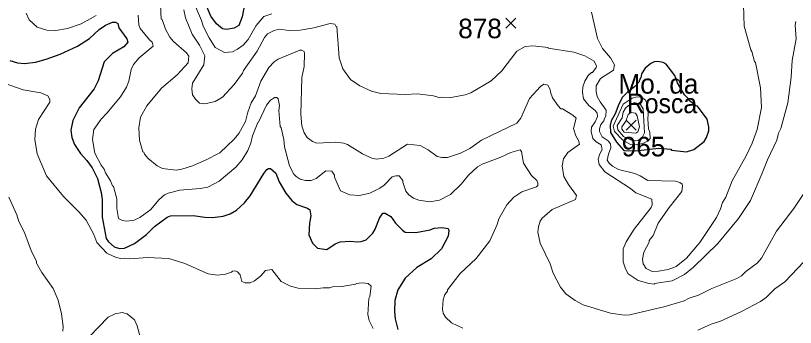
# Model space of a CAD drawing. Extents: x 265.7 to 292.1, y 7676.2 to 7704.2.
# Drawn here: x 267.652 to 270.846, y 7683.888 to 7685.164 of the extents above; entities that cross this region are included whole.
import ezdxf
from ezdxf.enums import TextEntityAlignment as Align

# ---------------------------------------------------------------- set-up
doc = ezdxf.new("R2010")
doc.units = 0
doc.header["$LTSCALE"] = 0.032
for name, color, linetype, lineweight in [('1', 7, 'Continuous', 25), ('2', 7, 'Continuous', 13), ('21', 7, 'Continuous', 25)]:
    doc.layers.add(name, color=color, linetype=linetype, lineweight=lineweight)
doc.layers.add('61', color=7, linetype='Continuous')

msp = doc.modelspace()

# ---------------------------------------------------------------- linework, layer by layer
at = {"layer": '1'}
for points in [[(268.5907, 7685.2156), (268.5804, 7685.1581), (268.5668, 7685.123), (268.5468, 7685.1118), (268.5157, 7685.1071), (268.4998, 7685.1095), (268.475, 7685.1302), (268.4519, 7685.1613), (268.416, 7685.2475)], [(267.6276, 7684.9802), (267.6587, 7684.9698), (267.6874, 7684.9682), (267.7337, 7684.973), (267.7768, 7684.985), (267.8343, 7685.0065), (267.9045, 7685.0384), (267.954, 7685.0696), (267.9939, 7685.1063), (268.0194, 7685.1246), (268.0489, 7685.1374), (268.0609, 7685.1374), (268.0705, 7685.131), (268.0752, 7685.1135), (268.1072, 7685.0688), (268.1119, 7685.0544), (268.0944, 7685.0352), (268.0481, 7685.0089), (268.0138, 7684.9738), (267.9899, 7684.8964), (267.9739, 7684.8645), (267.9125, 7684.7863), (267.8861, 7684.7344), (267.8773, 7684.6953), (267.8821, 7684.665), (267.8933, 7684.6363), (267.9172, 7684.5996), (267.9436, 7684.5708), (267.9659, 7684.5405), (267.9867, 7684.4974), (268.0018, 7684.44), (268.0058, 7684.4113), (268.0058, 7684.3394), (268.0226, 7684.2517), (268.0321, 7684.2373), (268.0553, 7684.2181), (268.0769, 7684.2101), (268.0976, 7684.2125), (268.1383, 7684.2309), (268.1878, 7684.2684), (268.2205, 7684.3003), (268.2723, 7684.3394), (268.2859, 7684.3442), (268.3785, 7684.3458)], [(268.5899, 7684.3977), (268.6123, 7684.4264), (268.6681, 7684.5174), (268.6809, 7684.5333), (268.6881, 7684.5373), (268.6961, 7684.5373), (268.7176, 7684.5182), (268.7312, 7684.4831), (268.7591, 7684.4368), (268.7838, 7684.4065), (268.8038, 7684.3905), (268.8477, 7684.3761), (268.8564, 7684.369), (268.8612, 7684.3442), (268.8556, 7684.3139), (268.8525, 7684.266), (268.8676, 7684.2325), (268.8884, 7684.2125), (268.9267, 7684.207), (268.961, 7684.2293), (268.9817, 7684.2381), (269.0216, 7684.2405), (269.052, 7684.2373), (269.0679, 7684.2389), (269.0879, 7684.2461), (269.115, 7684.274), (269.1246, 7684.29), (269.1429, 7684.3346), (269.1565, 7684.3546), (269.1661, 7684.3554), (269.1884, 7684.3418), (269.2083, 7684.3139), (269.2363, 7684.2852), (269.2483, 7684.278), (269.2913, 7684.2756), (269.3504, 7684.2876), (269.3664, 7684.2939), (269.3983, 7684.2971), (269.4238, 7684.2923), (269.4262, 7684.2844), (269.4238, 7684.2612), (269.3967, 7684.2086), (269.3544, 7684.1679), (269.2961, 7684.1335), (269.2483, 7684.0897), (269.2179, 7684.041), (269.2052, 7683.9979), (269.2036, 7683.9532), (269.2068, 7683.9229), (269.2179, 7683.8798)], [(268.3785, 7684.3458), (268.4264, 7684.3386), (268.4583, 7684.3378), (268.5014, 7684.3426), (268.5301, 7684.353), (268.5572, 7684.3681), (268.5899, 7684.3977)]]:
    msp.add_lwpolyline(points, dxfattribs=at)
msp.add_lwpolyline([(270.1436, 7684.6122), (270.1902, 7684.6103), (270.287, 7684.6209), (270.336, 7684.6165), (270.3391, 7684.6131), (270.4005, 7684.6059), (270.43, 7684.6163), (270.4731, 7684.649), (270.4819, 7684.6642), (270.4915, 7684.6921), (270.4923, 7684.7081), (270.4851, 7684.74), (270.446, 7684.7935), (270.438, 7684.7943), (270.4101, 7684.8174), (270.4093, 7684.8222), (270.3925, 7684.839), (270.3638, 7684.8884), (270.3526, 7684.9188), (270.3175, 7684.965), (270.3048, 7684.9722), (270.2824, 7684.9762), (270.2681, 7684.9746), (270.2537, 7684.9682), (270.2305, 7684.9483), (270.2162, 7684.9251), (270.2138, 7684.9084), (270.2106, 7684.9068), (270.205, 7684.8916), (270.1867, 7684.8717), (270.1595, 7684.8517), (270.138, 7684.8302), (270.1229, 7684.8008), (270.108, 7684.7612), (270.091, 7684.7329), (270.0872, 7684.7159), (270.0891, 7684.6858), (270.1132, 7684.6459)], close=True, dxfattribs=at)
at = {"layer": '2'}
for points in [[(268.7009, 7685.1709), (268.6681, 7685.1597), (268.6378, 7685.1238), (268.6043, 7685.0656), (268.5836, 7685.0432), (268.5604, 7685.0257), (268.5405, 7685.0153), (268.507, 7685.0129), (268.4694, 7685.0329), (268.4447, 7685.072), (268.42, 7685.1198), (268.4136, 7685.1438), (268.3697, 7685.2475)], [(268.2452, 7685.2076), (268.2484, 7685.1486), (268.2516, 7685.1478), (268.2652, 7685.1087), (268.2835, 7685.0752), (268.2979, 7685.0576), (268.3514, 7685.0113), (268.3609, 7684.9978), (268.3585, 7684.9698), (268.313, 7684.9219), (268.25, 7684.8661), (268.1886, 7684.7943), (268.1638, 7684.748), (268.1558, 7684.7049), (268.1598, 7684.6538), (268.1734, 7684.6059), (268.1766, 7684.6051), (268.1798, 7684.5964), (268.1941, 7684.5788), (268.2317, 7684.5485), (268.254, 7684.5373), (268.3099, 7684.5317), (268.3322, 7684.5349), (268.3769, 7684.5493), (268.4296, 7684.5716), (268.4886, 7684.602), (268.5476, 7684.6578), (268.5668, 7684.681), (268.5931, 7684.7304), (268.6027, 7684.7687), (268.6171, 7684.807), (268.6338, 7684.8358), (268.6562, 7684.8948), (268.6897, 7684.9507), (268.7112, 7684.9738), (268.7272, 7684.9858), (268.8158, 7685.0225), (268.8245, 7685.0225), (268.8333, 7685.0169), (268.8357, 7685.0089), (268.8333, 7684.9555), (268.8237, 7684.9108), (268.8205, 7684.7608), (268.8245, 7684.7129), (268.8333, 7684.6842), (268.8461, 7684.665), (268.8676, 7684.649), (268.886, 7684.6419), (268.9642, 7684.6458), (268.9961, 7684.6419), (269.0113, 7684.6363), (269.0727, 7684.598), (269.111, 7684.5796), (269.1302, 7684.5764), (269.1605, 7684.5796), (269.1812, 7684.5884), (269.2578, 7684.6371), (269.3089, 7684.6323), (269.3424, 7684.6147), (269.3791, 7684.5876)], [(270.2413, 7684.489), (270.3558, 7684.4855), (270.3726, 7684.4807), (270.3822, 7684.4743), (270.3846, 7684.4671), (270.3814, 7684.444), (270.3287, 7684.3785), (270.2848, 7684.3139), (270.2633, 7684.2644), (270.2473, 7684.2429), (270.2473, 7684.2365), (270.2258, 7684.1958), (270.2202, 7684.1671), (270.2234, 7684.1479), (270.2353, 7684.1288), (270.2601, 7684.1168), (270.2856, 7684.1176), (270.3255, 7684.1248), (270.3574, 7684.1375), (270.4005, 7684.1711), (270.4548, 7684.2349), (270.5226, 7684.337), (270.5402, 7684.3729), (270.5473, 7684.3985), (270.5609, 7684.4208), (270.5872, 7684.4879), (270.6447, 7684.59), (270.6694, 7684.6411), (270.6894, 7684.6969), (270.7077, 7684.7871), (270.7029, 7684.8677), (270.683, 7684.9714), (270.679, 7684.9754), (270.6686, 7685.0161), (270.6638, 7685.0241), (270.6367, 7685.1198), (270.6335, 7685.2076)], [(267.6954, 7685.1741), (267.7074, 7685.1462), (267.7401, 7685.1158), (267.78, 7685.1047), (267.8167, 7685.1031), (267.8646, 7685.1111), (267.9205, 7685.1294), (267.9811, 7685.1637)], [(268.1542, 7685.1661), (268.1566, 7685.1262), (268.1622, 7685.1103), (268.1997, 7685.064), (268.2117, 7685.0544), (268.2157, 7685.0384), (268.1574, 7684.9914), (268.1343, 7684.9642), (268.1247, 7684.9427), (268.1151, 7684.8948), (268.1056, 7684.8709), (268.0808, 7684.831), (268.0258, 7684.7639), (268.0018, 7684.74), (267.9723, 7684.6969), (267.9667, 7684.657), (267.9763, 7684.6012), (268.0018, 7684.5517), (268.0138, 7684.5357), (268.0194, 7684.5198), (268.0401, 7684.4879), (268.0481, 7684.4671), (268.0529, 7684.4647), (268.0657, 7684.4144), (268.0657, 7684.3745), (268.0729, 7684.3338), (268.0896, 7684.3251), (268.1056, 7684.3219), (268.1375, 7684.3259), (268.1606, 7684.337), (268.2053, 7684.3705), (268.238, 7684.4097), (268.2612, 7684.4296), (268.2763, 7684.4376), (268.3242, 7684.4495), (268.4072, 7684.4559), (268.4391, 7684.4615), (268.4854, 7684.4855), (268.554, 7684.5437), (268.5796, 7684.574), (268.6027, 7684.6123), (268.6155, 7684.6411), (268.6227, 7684.6714), (268.6434, 7684.7264), (268.6474, 7684.728), (268.6801, 7684.7975), (268.6953, 7684.8174), (268.7136, 7684.8286), (268.7216, 7684.8286), (268.728, 7684.823), (268.7328, 7684.7959), (268.7296, 7684.7751), (268.736, 7684.7105), (268.74, 7684.7049), (268.7503, 7684.657), (268.7535, 7684.6267), (268.7735, 7684.5485), (268.791, 7684.515), (268.8006, 7684.5046), (268.8174, 7684.495), (268.8397, 7684.4886), (268.862, 7684.4886), (268.8828, 7684.4974), (268.9227, 7684.5285), (268.9474, 7684.5269), (268.9578, 7684.511), (268.9586, 7684.503), (268.9825, 7684.4472), (269.0216, 7684.4304), (269.0599, 7684.4272), (269.103, 7684.4376), (269.1437, 7684.4575), (269.1613, 7684.4703), (269.194, 7684.5038), (269.21, 7684.5086), (269.2235, 7684.5078), (269.2387, 7684.4894), (269.2387, 7684.4815), (269.2506, 7684.4448), (269.2626, 7684.4296)], [(268.3402, 7685.1877), (268.3482, 7685.155), (268.3745, 7685.0879), (268.4056, 7685.0432), (268.4272, 7684.9986), (268.4232, 7684.9626), (268.3769, 7684.8868), (268.3737, 7684.8645), (268.3769, 7684.839), (268.3888, 7684.8214), (268.4056, 7684.8054), (268.4264, 7684.8022), (268.4694, 7684.8126), (268.4998, 7684.8302), (268.5468, 7684.882), (268.5812, 7684.9283), (268.5859, 7684.9395), (268.641, 7685.0177), (268.6713, 7685.0736), (268.6833, 7685.0887), (268.7104, 7685.1031), (268.7296, 7685.1079), (268.7727, 7685.1023), (268.8174, 7685.1047), (268.8732, 7685.1142), (268.9402, 7685.131), (268.9594, 7685.1286), (268.9634, 7685.1206), (268.9674, 7685.119), (268.9777, 7684.9906), (268.9921, 7684.9459), (269.024, 7684.9028), (269.0615, 7684.8757), (269.1094, 7684.8549), (269.1477, 7684.8453), (269.2483, 7684.8413), (269.2977, 7684.8429), (269.3632, 7684.835), (269.3855, 7684.8286), (269.3967, 7684.8302), (269.4286, 7684.827), (269.494, 7684.8398), (269.5164, 7684.8477), (269.5994, 7684.8972), (269.644, 7684.9371), (269.7047, 7685.0177), (269.739, 7685.0376), (269.7701, 7685.04), (269.834, 7685.0329), (269.834, 7685.0305), (269.9393, 7685.0137), (269.984, 7684.9993), (270.0215, 7684.9778), (270.0311, 7684.9571), (270.0303, 7684.9515)], [(270.0111, 7685.1773), (270.0358, 7685.0704), (270.0566, 7685.0289), (270.0885, 7684.9914), (270.1053, 7684.9618), (270.1013, 7684.9403), (270.0478, 7684.906), (270.0303, 7684.8757), (270.0303, 7684.8533), (270.0342, 7684.8326), (270.0462, 7684.8102), (270.0717, 7684.7767), (270.0702, 7684.752), (270.0638, 7684.7432), (270.0622, 7684.7336), (270.0494, 7684.7185), (270.0438, 7684.7001), (270.0438, 7684.6889), (270.055, 7684.6682), (270.0789, 7684.6506), (270.0885, 7684.6395), (270.0901, 7684.6219), (270.0805, 7684.5964), (270.0757, 7684.5716), (270.0829, 7684.5597), (270.0965, 7684.5477), (270.1212, 7684.5341), (270.1883, 7684.5174), (270.2106, 7684.5078), (270.2413, 7684.489)], [(269.9736, 7684.8501), (269.9784, 7684.823), (270.0007, 7684.7959), (270.0255, 7684.7751), (270.0342, 7684.7639), (270.035, 7684.7512), (270.0255, 7684.7288), (270.0111, 7684.7065), (270.0095, 7684.6897), (270.0167, 7684.6602), (270.0303, 7684.6474), (270.051, 7684.6355), (270.0542, 7684.6155), (270.0446, 7684.598), (270.0382, 7684.5756), (270.043, 7684.5549), (270.0654, 7684.5245), (270.1707, 7684.4559), (270.193, 7684.4384), (270.2577, 7684.412), (270.2601, 7684.3889), (270.2561, 7684.3785), (270.1859, 7684.2892), (270.1531, 7684.2381), (270.1404, 7684.2086), (270.1412, 7684.1559), (270.1499, 7684.1272), (270.1611, 7684.1072), (270.2026, 7684.0793), (270.2457, 7684.0673), (270.2688, 7684.0649), (270.2696, 7684.0673), (270.3415, 7684.0785), (270.3925, 7684.1048), (270.4292, 7684.1343), (270.529, 7684.2317), (270.6128, 7684.3338), (270.6622, 7684.4065), (270.7109, 7684.5182), (270.7317, 7684.574), (270.77, 7684.6538), (270.7779, 7684.6826), (270.7867, 7684.7017), (270.8155, 7684.807), (270.829, 7684.9124), (270.833, 7684.9794), (270.849, 7685.0688), (270.845, 7685.1246), (270.8482, 7685.1398)], [(270.0303, 7684.9515), (270.0151, 7684.9315), (270.0111, 7684.9315), (269.9975, 7684.918), (269.9832, 7684.8948), (269.9752, 7684.8725), (269.9736, 7684.8501)], [(267.6084, 7684.886), (267.6827, 7684.8605), (267.7545, 7684.8477), (267.7832, 7684.835), (267.792, 7684.8198), (267.7912, 7684.8094), (267.7457, 7684.7384), (267.7329, 7684.6985)], [(269.7055, 7684.724), (269.7214, 7684.744), (269.7566, 7684.8246), (269.802, 7684.8741), (269.8164, 7684.8836), (269.8324, 7684.8796), (269.8419, 7684.8613), (269.8427, 7684.8501), (269.8507, 7684.8278), (269.8739, 7684.7943), (269.8858, 7684.7823), (269.8922, 7684.7815), (269.9345, 7684.756), (269.9489, 7684.744), (269.9377, 7684.7017), (269.9465, 7684.6714), (269.9584, 7684.6522), (269.9616, 7684.6371), (269.9146, 7684.6036), (269.897, 7684.5772), (269.8906, 7684.5485), (269.8978, 7684.5054), (269.9169, 7684.4719), (269.9497, 7684.4272), (269.9457, 7684.4105), (269.8499, 7684.3697), (269.8084, 7684.3354), (269.8004, 7684.3219), (269.7933, 7684.2995), (269.7917, 7684.2772), (269.8004, 7684.2325), (269.8419, 7684.1479), (269.8547, 7684.1096), (269.8834, 7684.0522), (269.9058, 7684.025), (269.9441, 7683.9979), (269.9776, 7683.9803), (270.0893, 7683.946), (270.1452, 7683.9381), (270.1675, 7683.9396), (270.3127, 7683.9732), (270.3909, 7683.9971), (270.4117, 7684.0075), (270.45, 7684.0202), (270.5043, 7684.0466), (270.6064, 7684.0881), (270.6255, 7684.0992), (270.6431, 7684.116), (270.6902, 7684.1511), (270.7077, 7684.1711), (270.7692, 7684.282), (270.8394, 7684.3745), (270.8921, 7684.4527)], [(269.3791, 7684.5876), (269.3983, 7684.5828), (269.4206, 7684.5828), (269.4749, 7684.6004), (269.5132, 7684.6203), (269.5603, 7684.6538), (269.7055, 7684.724)], [(267.7329, 7684.6985), (267.7305, 7684.657), (267.7401, 7684.598), (267.7784, 7684.5086), (267.8478, 7684.4232), (267.9109, 7684.361), (267.9412, 7684.3259)], [(269.4765, 7684.4743), (269.5076, 7684.511), (269.5435, 7684.5445), (269.5635, 7684.5557), (269.6393, 7684.5844), (269.6808, 7684.6036), (269.7191, 7684.6147), (269.7246, 7684.6075), (269.7326, 7684.5597), (269.7653, 7684.5094), (269.7869, 7684.4894), (269.7909, 7684.4799), (269.7909, 7684.4687), (269.7861, 7684.4631), (269.7254, 7684.4424), (269.6927, 7684.42), (269.6648, 7684.3897), (269.6321, 7684.3315), (269.6249, 7684.3091), (269.5946, 7684.2421), (269.5379, 7684.1703), (269.4733, 7684.108), (269.4214, 7684.0418), (269.4214, 7684.0354), (269.4102, 7684.0218), (269.4031, 7684.0011), (269.4007, 7683.9628), (269.4039, 7683.946), (269.4126, 7683.9293), (269.4374, 7683.9061), (269.4845, 7683.8846)], [(269.2626, 7684.4296), (269.2818, 7684.4168), (269.3041, 7684.4089), (269.3488, 7684.4017), (269.3887, 7684.4089), (269.4334, 7684.4312), (269.4765, 7684.4743)], [(267.8454, 7683.8718), (267.847, 7683.8918), (267.8391, 7683.9436), (267.8263, 7683.9995), (267.8055, 7684.0474), (267.7593, 7684.1128), (267.7369, 7684.1511), (267.7369, 7684.1583), (267.7162, 7684.199), (267.689, 7684.2724), (267.6635, 7684.3251), (267.6571, 7684.349), (267.6236, 7684.4208)], [(267.9412, 7684.3259), (267.9723, 7684.2676), (267.9843, 7684.2357), (268.025, 7684.191), (268.0641, 7684.1735), (268.0832, 7684.1695), (268.096, 7684.1711), (268.1199, 7684.1679), (268.1918, 7684.1735), (268.2795, 7684.1695), (268.345, 7684.1487), (268.4407, 7684.1072), (268.479, 7684.1016), (268.5109, 7684.1056), (268.5365, 7684.1136), (268.5405, 7684.1184), (268.5508, 7684.1192), (268.5604, 7684.1152), (268.5716, 7684.1032), (268.5788, 7684.0761), (268.5915, 7684.0705), (268.6131, 7684.0705), (268.6298, 7684.0777), (268.6546, 7684.0976), (268.6753, 7684.12), (268.7009, 7684.1248), (268.74, 7684.0753), (268.7775, 7684.057), (268.8094, 7684.0482), (268.8796, 7684.045), (268.9115, 7684.0498), (268.9371, 7684.0498), (268.9498, 7684.0538), (268.9881, 7684.0546), (269.0456, 7684.0649), (269.0464, 7684.0673), (269.0711, 7684.0697), (269.0966, 7684.0673), (269.1078, 7684.0562), (269.103, 7684.0139), (269.0982, 7684.0059), (269.095, 7683.9412), (269.0998, 7683.9165), (269.1166, 7683.883)], [(270.4468, 7683.8758), (270.5019, 7683.9013), (270.5394, 7683.9133), (270.6255, 7683.9524), (270.7037, 7683.9939), (270.7285, 7684.0115), (270.7628, 7684.045), (270.8027, 7684.0745), (270.8825, 7684.1575)], [(268.1646, 7683.8383), (268.1495, 7683.8942), (268.1391, 7683.9181), (268.108, 7683.9428), (268.0888, 7683.9484), (268.0593, 7683.9436), (268.0314, 7683.9293), (267.954, 7683.8503)]]:
    msp.add_lwpolyline(points, dxfattribs=at)
for points in [[(270.1411, 7684.8006), (270.0995, 7684.7111), (270.1059, 7684.6898), (270.1396, 7684.6541), (270.1714, 7684.6366), (270.1939, 7684.6347), (270.2201, 7684.6403), (270.2425, 7684.6497), (270.2519, 7684.661), (270.25, 7684.6872), (270.2444, 7684.7003), (270.2417, 7684.7416), (270.2441, 7684.7799), (270.2409, 7684.7991), (270.2329, 7684.8182), (270.2162, 7684.8302), (270.1978, 7684.831), (270.1771, 7684.8254)], [(270.1427, 7684.6688), (270.1745, 7684.6539), (270.1933, 7684.651), (270.2029, 7684.6529), (270.2194, 7684.6674), (270.2282, 7684.6834), (270.2226, 7684.7815), (270.2122, 7684.7999), (270.1875, 7684.8086), (270.1627, 7684.7951), (270.1508, 7684.7847), (270.1412, 7684.7687), (270.1372, 7684.7448), (270.1164, 7684.7137), (270.1188, 7684.6961)], [(270.1614, 7684.7591), (270.1518, 7684.7314), (270.1358, 7684.709), (270.1347, 7684.6983), (270.1454, 7684.6866), (270.1923, 7684.6824), (270.2008, 7684.6877), (270.2072, 7684.709), (270.1987, 7684.7538), (270.1914, 7684.7647), (270.1723, 7684.7671)]]:
    msp.add_lwpolyline(points, close=True, dxfattribs=at)
at = {"layer": '21'}
for p, q in [((269.6603, 7685.1531), (269.7015, 7685.1119)), ((269.7015, 7685.1531), (269.6603, 7685.1119)), ((270.1531, 7684.7359), (270.1943, 7684.6947)), ((270.1943, 7684.7359), (270.1531, 7684.6947))]:
    msp.add_line(p, q, dxfattribs=at)

# ---------------------------------------------------------------- texts
at = {"layer": '61'}
for s, p in [('878', (269.5543, 7685.071)), ('Mo. da ', (270.3001, 7684.8444)), ('965', (270.2242, 7684.5877))]:
    msp.add_text(s, height=0.08, dxfattribs=at).set_placement(p, align=Align.CENTER)
at = {"layer": '61', "width": 0.95}
msp.add_text('Rosca', height=0.08, dxfattribs=at).set_placement((270.3, 7684.7644), align=Align.CENTER)

doc.saveas('drawing.dxf')
